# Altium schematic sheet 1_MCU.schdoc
size 309 x 223 mm; Symbol: Sheet-Symbol_A4; Device: Sheet-Symbol_A4; @Page Name: MCU; @Create Date: 2023-05-13; @Page Count: 3; @Page No: 2; @Project Name: STM32_Wave&DSO; @Schematic Name: STM32_Wave&amp;DSO; @Update Date: 2023-05-14; Company: DGUT; Drawed: veis; Page Size: A4; Version: V1.0
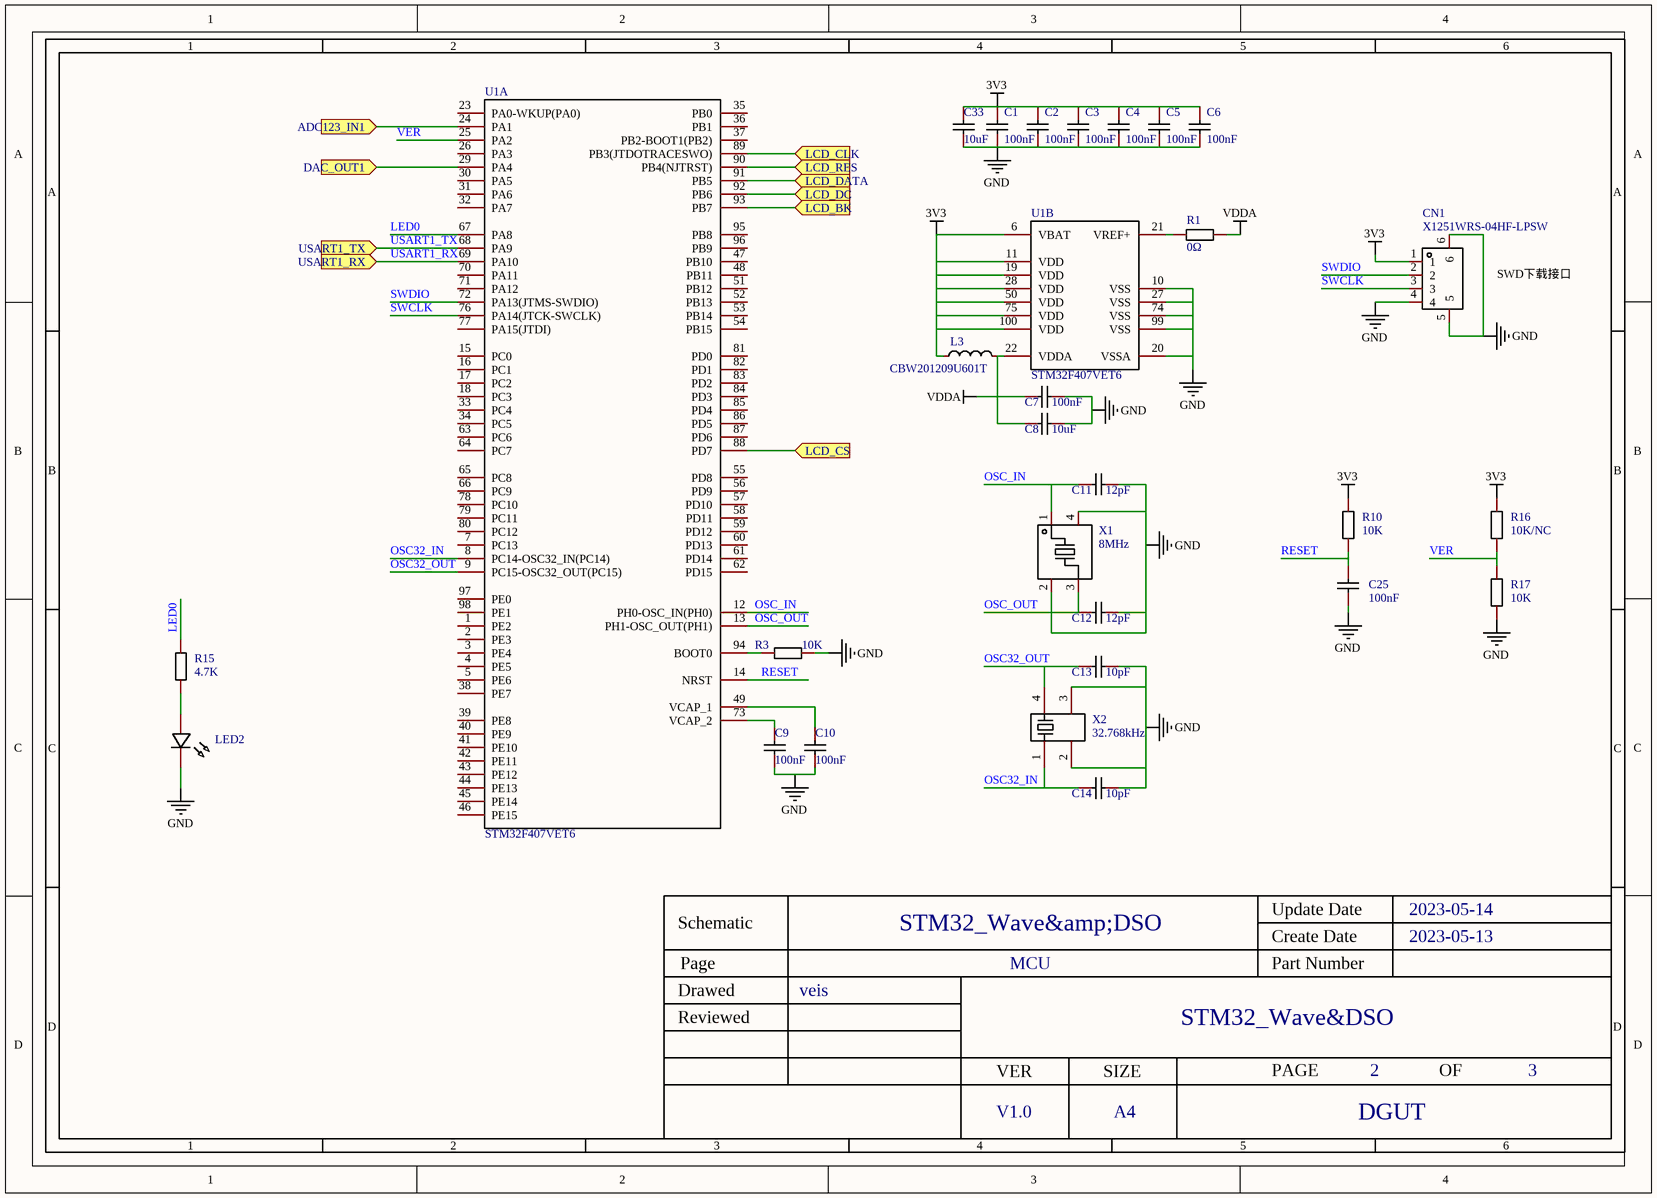
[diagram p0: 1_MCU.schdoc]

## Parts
C1  100nF  [C0603]
C2  100nF  [C0603]
C3  100nF  [C0603]
C4  100nF  [C0603]
C5  100nF  [C0603]
C6  100nF  [C0603]
C7  100nF  [C0603]
C8  10uF  [C0805]
C9  100nF  [C0603]
C10  100nF  [C0603]
C11  12pF  [C0603]
C12  12pF  [C0603]
C13  10pF  [C0603]
C14  10pF  [C0603]
C25  100nF  [C0603]
C33  10uF  [C0805]
CN1  X1251WRS-04HF-LPSW  [CONN-SMD_4P-P1.25_X1251WRS-04HF-LPSW]
L3  CBW201209U601T  [L0805]
LED2  LED_0603-R  [LED_0603]  (value not drawn)
R1  0Ω  [R0603]
R3  10K  [R0603]
R10  10K  [R0603]
R15  4.7K  [R0603]
R16  10K/NC  [R0603]
R17  10K  [R0603]
U1  STM32F407VET6  [LQFP-100_L14.0-W14.0-P0.50-LS16.0-BL]  (parts A,B of 2)
X1  8MHz  [OSC-SMD_4P-L3.2-W2.5-BL]
X2  32.768kHz  [MC-146_4P-L6.7-W1.5-P0.85-BL]

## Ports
ADC123_IN1 (in), DAC_OUT1 (in), LCD_BK (in), LCD_CLK (in), LCD_CS (in), LCD_DATA (in), LCD_DC (in), LCD_RES (in), USART1_RX (in), USART1_TX (in)

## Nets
3V3: C1.2 C2.2 C3.2 C4.2 C5.2 C6.2 C33.2 CN1.1 L3.1 R10.1 R16.1 U1.6(VBAT) U1.11(VDD) U1.19(VDD) U1.28(VDD) U1.50(VDD) U1.75(VDD) U1.100(VDD)
GND: C1.1 C2.1 C3.1 C4.1 C5.1 C6.1 C7.1 C8.2 C9.2 C10.2 C11.1 C12.1 C13.1 C14.1 C25.2 C33.1 CN1.4 CN1.5 CN1.6 LED2.1(C) R3.2 R17.2 U1.10(VSS) U1.20(VSSA) U1.27(VSS) U1.74(VSS) U1.99(VSS) X1.2(GND) X1.4(GND) X2.2 X2.3
VDDA: C7.2 C8.1 L3.2 R1.2 U1.22(VDDA)
ADC123_IN1: U1.24(PA1) ; port ADC123_IN1
DAC_OUT1: U1.29(PA4) ; port DAC_OUT1
LCD_BK: U1.93(PB7) ; port LCD_BK
LCD_CLK: U1.89(PB3(JTDOTRACESWO)) ; port LCD_CLK
LCD_CS: U1.88(PD7) ; port LCD_CS
LCD_DATA: U1.91(PB5) ; port LCD_DATA
LCD_DC: U1.92(PB6) ; port LCD_DC
LCD_RES: U1.90(PB4(NJTRST)) ; port LCD_RES
LED0: R15.2 U1.67(PA8)
OSC32_IN: C14.2 U1.8(PC14-OSC32_IN(PC14)) X2.1
OSC32_OUT: C13.2 U1.9(PC15-OSC32_OUT(PC15)) X2.4
OSC_IN: C11.2 U1.12(PH0-OSC_IN(PH0)) X1.1
OSC_OUT: C12.2 U1.13(PH1-OSC_OUT(PH1)) X1.3
RESET: C25.1 R10.2 U1.14(NRST)
SWCLK: CN1.3 U1.76(PA14(JTCK-SWCLK))
SWDIO: CN1.2 U1.72(PA13(JTMS-SWDIO))
USART1_RX: U1.69(PA10) ; port USART1_RX
USART1_TX: U1.68(PA9) ; port USART1_TX
VER: R16.2 R17.1 U1.25(PA2)
NetC9_1: C9.1 U1.73(VCAP_2)
NetC10_1: C10.1 U1.49(VCAP_1)
NetLED2_2: LED2.2(A) R15.1
NetR1_1: R1.1 U1.21(VREF+)
NetR3_1: R3.1 U1.94(BOOT0)

Not connected (* = marked no-connect by the designer): U1 1(PE2) 2(PE3) 3(PE4) 4(PE5) 5(PE6) 7(PC13) 15(PC0) 16(PC1) 17(PC2) 18(PC3) 23(PA0-WKUP(PA0)) 26(PA3) 30(PA5) 31(PA6) 32(PA7) 33(PC4) 34(PC5) 35(PB0) 36(PB1) 37(PB2-BOOT1(PB2)) 38(PE7) 39(PE8) 40(PE9) 41(PE10) 42(PE11) 43(PE12) 44(PE13) 45(PE14) 46(PE15) 47(PB10) 48(PB11) 51(PB12) 52(PB13) 53(PB14) 54(PB15) 55(PD8) 56(PD9) 57(PD10) 58(PD11) 59(PD12) 60(PD13) 61(PD14) 62(PD15) 63(PC6) 64(PC7) 65(PC8) 66(PC9) 70(PA11) 71(PA12) 77(PA15(JTDI)) 78(PC10) 79(PC11) 80(PC12) 81(PD0) 82(PD1) 83(PD2) 84(PD3) 85(PD4) 86(PD5) 87(PD6) 95(PB8) 96(PB9) 97(PE0) 98(PE1)

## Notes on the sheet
- (near CN1) SWD下载接口

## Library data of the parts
C1-C7 C9-C14 C25 = 0603B104K500NT: 容值:100nF;精度:±10%;额定电压:50V;材质(温度系数):X7R;; Manufacturer: FH(风华); Add into BOM: yes; Tolerance: ±10%; Voltage Rated: 50V; Temperature Coefficient: X7R
C8 C33 = GRM21BR61H106KE43L: 容值:10uF;精度:±10%;额定电压:50V;材质(温度系数):X5R;; Manufacturer: muRata(村田); Add into BOM: yes; Tolerance: ±10%; Voltage Rated: 50V; Temperature Coefficient: X5R
CN1 = X1251WRS-04HF-LPSW: 参考系列:GH;间距:1.25mm;插针结构:1x4P;排数:1;每排PIN数:4;行距:-;公母:母型插口;安装方式:卧贴;额定电流:1A;触头材质:磷青铜;触头镀层:锡;工作温度范围:-40℃~+110℃;焊接温度(最大值):260℃;; Manufacturer: XKB Connectivity(中国星坤); Add into BOM: yes; Reference Series: GH; Pitch: 1.25mm; Pins Structure: 1x4P; Number of PINs Per Row: 4; Gender: 母型插口; Current Rating (Max): 1A; Welding Temperature (Max): 260℃
L3 = 磁珠 0805 600Ω@100MHz CBW201209U601T: Add into BOM: yes
LED2 = LED_0603-R: Symbol: LED_R; Convert to PCB: yes
R1 R3 R10 R16 R17 = 0603WAF0000T5E: 电阻类型:厚膜电阻;阻值:0Ω;精度:±1%;功率:100mW;; Manufacturer: UNI-ROYAL(厚声); Add into BOM: yes; Tolerance: ±1%; Power(Watts): 100mW; Overload Voltage (Max): 75V
R15 = Res_0603: Symbol: 电阻; Convert to PCB: yes
U1 = STM32F407VET6: CPU内核:ARM Cortex-M4;CPU最大主频:168MHz;程序存储容量:512KB;程序存储器类型:FLASH;RAM总容量:192KB;GPIO端口数量:82;; Manufacturer: ST(意法半导体); Add into BOM: yes; CPU Maximum Speed: 168MHz; Operating Voltage Range: 1.8V~3.6V; Program Storage Size: 512KB; Program Memory Type: FLASH; RAM Size: 192KB; GPIO Ports Number: 82; ADC (Bit): 12bit; Universal Serial Bus: 有; Peripheral/Function: DMA；LCD/LED驱动；PWM
X1 = X32258MOB4SI: 频率:8MHz;频率公差:±10ppm;负载电容:12pF;; Manufacturer: YXC(扬兴晶振); Add into BOM: yes; Crystal Type: 贴片无源晶振; Frequency Tolerance: ±10ppm; Frequency Stability: ±30ppm; Load Capacitance: 12pF; Equivalent Series Resistance (ESR): 150Ω
X2 = M132768PWPAC: 频率:32.768kHz;频率公差:±20ppm;负载电容:12.5pF;; Manufacturer: JYJE(晶友嘉); Add into BOM: yes; Crystal Type: 贴片无源晶振; Frequency Tolerance: ±20ppm; Load Capacitance: 12.5pF; Equivalent Series Resistance (ESR): 65kΩ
